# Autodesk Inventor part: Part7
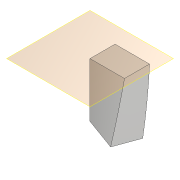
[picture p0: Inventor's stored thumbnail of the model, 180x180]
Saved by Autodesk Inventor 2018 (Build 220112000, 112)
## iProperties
Created: 2015-07
Part Number: Part7
Material: Generic
Document SubType Name: Modeling
Designer: Sandeep
Density: 1 g/cm^3
Appearance: Default
Author: Sandeep
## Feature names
1. Sweep1
## Parameters: d0 = 0, d1 = 20 deg
